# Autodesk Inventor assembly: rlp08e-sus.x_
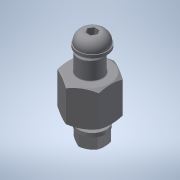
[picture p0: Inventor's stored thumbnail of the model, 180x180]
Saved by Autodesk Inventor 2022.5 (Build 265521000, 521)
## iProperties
Part Number: rlp08e-sus.x_
Material: 一般
Document SubType Name: Assembly
Designer: ImaoCorp
Sending System: SOLIDWORKS 2017-2017317
MC: AMD64
MC_MODEL: Intel64 Family 6 Model 60 Stepping 3, GenuineIntel
OS: Windows_NT
FRU: Parasolid Version 29.0, build 201,  4-17-2017
FORMAT: text
GUISE: transmit
KEY: rlp08e-sus
FILE: rlp08e-sus.x_t
DATE: Wed Sep 04 15:58:43 2019
Author: ImaoCorp
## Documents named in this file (3)
- X:\14_SW2022-Inv2022\00_全2023-1023新製品(TCC)まで\r\rlp08e-sus\RLP08E-SUS.iam
- X:\14_SW2022-Inv2022\00_全2023-1023新製品(TCC)まで\r\rlp08e-sus\rlp08e-sus_01.ipt
- X:\14_SW2022-Inv2022\00_全2023-1023新製品(TCC)まで\r\rlp08e-sus\rlp08e-sus_02.ipt
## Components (2 placed, 2 different names)
1. rlp08e-sus_01
2. rlp08e-sus_02
